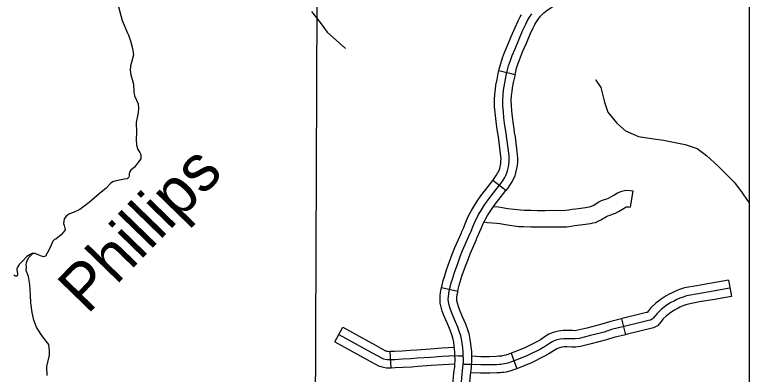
# Model space of a CAD drawing. Extents: x 670147 to 673275, y 705573 to 707613.
# Drawn here: x 672088.3 to 672221.9, y 706242.1 to 706307.4 of the extents above; entities that cross this region are included whole.
import ezdxf

# ---------------------------------------------------------------- set-up
doc = ezdxf.new("R2010")
doc.units = 0
for name, color, linetype in [('31', 7, 'Continuous'), ('32', 7, 'Continuous'), ('35', 7, 'Continuous'), ('45', 7, 'Continuous'), ('46', 7, 'Continuous'), ('5', 7, 'Continuous'), ('R_NoPlot', 7, 'Continuous')]:
    doc.layers.add(name, color=color, linetype=linetype)

msp = doc.modelspace()

# ---------------------------------------------------------------- linework, layer by layer
at = {"layer": '31'}
for p, q in [((672176.39, 706297.26), (672179.32, 706296.57)), ((672177.64, 706275.48), (672175.27, 706277.31)), ((672175.27, 706277.31), (672175.27, 706277.31)), ((672165.96, 706257.83), (672168.89, 706257.16))]:
    msp.add_line(p, q, dxfattribs=at)
for points in [[(672183.1, 706305.95), (672183.21, 706306.16), (672183.61, 706306.7), (672183.96, 706307.18), (672184.57, 706307.76), (672185.16, 706308.23), (672185.81, 706308.68), (672186.41, 706309.04), (672188.06, 706309.98), (672190.48, 706311.09), (672191, 706311.39)], [(672171.76, 706269.14), (672172.18, 706270.11), (672172.42, 706270.58), (672172.7, 706271.12), (672173.05, 706271.68), (672173.39, 706272.25), (672173.78, 706272.84), (672174.32, 706273.61), (672175.19, 706274.75), (672176.73, 706276.75), (672177.14, 706277.33), (672177.45, 706277.82), (672177.66, 706278.21), (672177.85, 706278.66), (672177.98, 706279.07), (672178.14, 706279.76), (672178.22, 706280.19), (672178.27, 706280.74), (672178.28, 706281.28), (672178.23, 706281.82), (672177.85, 706284.93), (672177.71, 706285.81), (672177.42, 706287.68), (672177.3, 706288.69), (672177.2, 706289.8), (672177.1, 706290.85), (672177.08, 706291.86), (672177.15, 706292.9), (672177.24, 706293.68), (672177.34, 706294.38), (672177.52, 706295.37), (672177.73, 706296.4), (672177.92, 706297.19), (672178.16, 706298.15), (672178.49, 706299.09), (672178.83, 706300.04), (672179.32, 706301.24), (672180, 706302.85), (672180.7, 706304.47), (672181.26, 706305.69), (672181.6, 706306.36), (672181.95, 706306.97), (672182.39, 706307.58)], [(672176.39, 706297.26), (672176.46, 706297.55), (672176.73, 706298.58), (672177.07, 706299.58), (672177.42, 706300.57), (672177.93, 706301.82), (672178.63, 706303.44), (672179.33, 706305.08), (672179.91, 706306.34), (672180.28, 706307.07), (672180.48, 706307.43)], [(672179.32, 706296.57), (672179.38, 706296.83), (672179.6, 706297.72), (672179.9, 706298.59), (672180.23, 706299.51), (672180.7, 706300.66), (672181.38, 706302.26), (672182.07, 706303.86), (672182.61, 706305.04), (672182.92, 706305.65), (672183.1, 706305.95)], [(672176.13, 706286.22), (672175.93, 706287.48), (672175.81, 706288.53), (672175.7, 706289.66), (672175.61, 706290.76), (672175.58, 706291.89), (672175.66, 706293.04), (672175.75, 706293.86), (672175.86, 706294.62), (672176.05, 706295.66), (672176.27, 706296.72), (672176.39, 706297.26)], [(672179.32, 706296.57), (672179.2, 706296.08), (672179, 706295.08), (672178.82, 706294.14), (672178.73, 706293.49), (672178.64, 706292.76), (672178.58, 706291.82), (672178.6, 706290.93), (672178.69, 706289.93), (672178.79, 706288.85), (672178.91, 706287.89), (672179.09, 706286.68)], [(672179.09, 706286.68), (672179.19, 706286.04), (672179.34, 706285.14), (672179.73, 706281.98), (672179.78, 706281.32), (672179.77, 706280.66), (672179.71, 706279.99), (672179.61, 706279.44), (672179.43, 706278.67), (672179.26, 706278.15), (672179.02, 706277.56), (672178.74, 706277.06), (672178.38, 706276.5), (672177.94, 706275.86), (672177.64, 706275.48)], [(672175.27, 706277.31), (672175.52, 706277.64), (672175.89, 706278.17), (672176.16, 706278.59), (672176.31, 706278.85), (672176.44, 706279.17), (672176.53, 706279.47), (672176.67, 706280.07), (672176.73, 706280.39), (672176.77, 706280.82), (672176.78, 706281.23), (672176.74, 706281.67), (672176.36, 706284.72), (672176.23, 706285.57), (672176.13, 706286.22)], [(672169.66, 706268.01), (672169.94, 706268.65), (672170.38, 706269.73), (672170.82, 706270.75), (672171.08, 706271.26), (672171.4, 706271.86), (672171.77, 706272.46), (672172.11, 706273.04), (672172.54, 706273.69), (672173.11, 706274.5), (672174, 706275.67), (672175.27, 706277.31)], [(672172.4, 706266.79), (672172.7, 706267.47), (672173.15, 706268.56), (672173.54, 706269.48), (672173.75, 706269.9), (672174, 706270.37), (672174.33, 706270.9), (672174.66, 706271.45), (672175.02, 706272), (672175.53, 706272.73), (672176.38, 706273.84), (672177.64, 706275.48)], [(672165.96, 706257.83), (672166.06, 706258.28), (672166.28, 706259.08), (672166.48, 706259.77), (672166.88, 706261.04), (672167.48, 706262.74), (672167.97, 706264), (672168.39, 706265.11), (672169.56, 706267.8), (672169.66, 706268.01)], [(672169.56, 706240.68), (672169.7, 706242.08), (672169.84, 706243.33), (672169.87, 706243.84), (672169.92, 706244.41), (672169.92, 706244.98), (672169.9, 706245.42), (672169.9, 706246.13), (672169.82, 706246.89), (672169.65, 706248.14), (672169.46, 706249.06), (672169.25, 706249.73), (672168.91, 706250.65), (672168.34, 706251.99), (672167.79, 706253.32), (672167.53, 706254.01), (672167.36, 706254.65), (672167.22, 706255.22), (672167.18, 706255.68), (672167.21, 706256.17), (672167.26, 706256.69), (672167.36, 706257.21), (672167.52, 706257.92), (672167.72, 706258.68), (672167.92, 706259.33), (672168.3, 706260.57), (672168.89, 706262.21), (672169.37, 706263.46), (672169.78, 706264.55), (672170.94, 706267.19), (672171.32, 706268.06), (672171.76, 706269.14)], [(672168.89, 706257.16), (672168.98, 706257.56), (672169.16, 706258.27), (672169.35, 706258.89), (672169.73, 706260.1), (672170.29, 706261.69), (672170.78, 706262.92), (672171.17, 706263.98), (672172.31, 706266.59), (672172.4, 706266.79)], [(672168.27, 706247.19), (672168.18, 706247.88), (672168, 706248.68), (672167.83, 706249.24), (672167.51, 706250.1), (672166.95, 706251.41), (672166.39, 706252.77), (672166.1, 706253.55), (672165.91, 706254.28), (672165.73, 706254.99), (672165.68, 706255.66), (672165.71, 706256.29), (672165.78, 706256.91), (672165.89, 706257.51), (672165.96, 706257.83)], [(672168.89, 706257.16), (672168.83, 706256.91), (672168.75, 706256.48), (672168.7, 706256.05), (672168.69, 706255.7), (672168.7, 706255.46), (672168.81, 706255.03), (672168.96, 706254.47), (672169.19, 706253.87), (672169.72, 706252.57), (672170.3, 706251.2), (672170.67, 706250.21), (672170.91, 706249.45), (672171.13, 706248.39), (672171.24, 706247.58)], [(672167.94, 706236.81), (672167.91, 706237.86), (672167.93, 706238.76), (672167.97, 706239.67), (672168.07, 706240.82), (672168.21, 706242.24), (672168.35, 706243.46), (672168.38, 706243.95), (672168.42, 706244.47), (672168.42, 706244.94), (672168.4, 706245.38), (672168.4, 706246.05), (672168.33, 706246.71), (672168.27, 706247.19)], [(672171.24, 706247.58), (672171.31, 706247.07), (672171.4, 706246.22), (672171.4, 706245.46), (672171.42, 706245.01), (672171.42, 706244.34), (672171.37, 706243.73), (672171.34, 706243.2), (672171.19, 706241.93), (672171.06, 706240.54), (672170.97, 706239.48), (672170.93, 706238.66), (672170.91, 706237.86), (672170.94, 706236.9)]]:
    msp.add_lwpolyline(points, dxfattribs=at)
at = {"layer": '32'}
for p, q in [((672146.56, 706247.98), (672148.01, 706250.61)), ((672156.77, 706243.23), (672156.63, 706246.23))]:
    msp.add_line(p, q, dxfattribs=at)
for points in [[(672148.01, 706250.61), (672153.93, 706247.33), (672155.79, 706246.33), (672155.87, 706246.3), (672156.02, 706246.26), (672156.2, 706246.24), (672156.57, 706246.22), (672156.63, 706246.23)], [(672147.28, 706249.29), (672153.21, 706246.02), (672155.15, 706244.98), (672155.39, 706244.88), (672155.72, 706244.79), (672156.07, 706244.74), (672156.57, 706244.72), (672157.44, 706244.76), (672158.87, 706244.84), (672160.37, 706244.94), (672161.54, 706245.02), (672163.98, 706245.18), (672166.11, 706245.34), (672167.28, 706245.41), (672168.41, 706245.45), (672169.02, 706245.44), (672169.9, 706245.42)], [(672146.56, 706247.98), (672152.49, 706244.7), (672154.51, 706243.62), (672154.9, 706243.45), (672155.42, 706243.32), (672155.94, 706243.25), (672156.57, 706243.22), (672156.77, 706243.23)], [(672156.63, 706246.23), (672157.37, 706246.26), (672158.78, 706246.34), (672160.27, 706246.43), (672161.44, 706246.51), (672163.87, 706246.68), (672166.01, 706246.84), (672168.29, 706246.97)], [(672156.77, 706243.23), (672157.52, 706243.26), (672158.96, 706243.34), (672160.47, 706243.44), (672161.64, 706243.52), (672164.09, 706243.69), (672166.21, 706243.84), (672168.4, 706243.97)]]:
    msp.add_lwpolyline(points, dxfattribs=at)
at = {"layer": '35'}
for points in [[(672108.93, 706303.87), (672107.93, 706306.31), (672107.21, 706309.07)], [(672142.33, 706308.04), (672143.91, 706306.01), (672145.15, 706304.24), (672148.5, 706301.28)], [(672108.93, 706303.87), (672109.4, 706302.7), (672109.77, 706301.29), (672109.94, 706300.15), (672109.6, 706299), (672109.4, 706298.13), (672109.34, 706297.36), (672109.47, 706296.52), (672109.91, 706294.81), (672110.01, 706293.4), (672110.11, 706292.66), (672110.48, 706291.92), (672110.75, 706291.25), (672110.81, 706290.38), (672110.75, 706289.64), (672110.41, 706287.82), (672110.48, 706286.04), (672110.41, 706284.8), (672110.48, 706283.68), (672110.71, 706282.95), (672111.08, 706282.4), (672111.27, 706282.04), (672111.24, 706281.22), (672110.85, 706280.7), (672110.14, 706279.71), (672109.47, 706279.18), (672109.2, 706278.81), (672109.13, 706278.5), (672109.13, 706278.14), (672109.07, 706277.87), (672108.77, 706277.6), (672108.3, 706277.5), (672107.39, 706277.36), (672106.52, 706277.16), (672106.11, 706277.03), (672105.71, 706276.69), (672104.94, 706275.89), (672103.66, 706274.84), (672101.88, 706273.27), (672100.17, 706271.99), (672099.11, 706271.55), (672098.31, 706271.23), (672097.72, 706270.86), (672097.31, 706270.3), (672097.17, 706269.46), (672097.29, 706269.1), (672097.44, 706268.64), (672097.51, 706268.31), (672097.39, 706268.13), (672096.78, 706267.39), (672096.18, 706266.92), (672095.81, 706266.65), (672095.54, 706266.55), (672095.24, 706266.28), (672095.1, 706265.85), (672094.7, 706264.97), (672094.23, 706264.1), (672093.9, 706263.56), (672093.53, 706263.43), (672093.22, 706263.5), (672092.57, 706263.79), (672092.07, 706263.99), (672091.83, 706264.01)], [(672193.97, 706295.62), (672194.03, 706295.55), (672194.9, 706294.18), (672195.62, 706291.5), (672196.2, 706289.7), (672197.86, 706287.68), (672199.44, 706286.31), (672201.75, 706285.29), (672203.7, 706285.01), (672206.3, 706284.64), (672210.27, 706283.85), (672212.44, 706283.13), (672214.17, 706281.83), (672216.26, 706279.88), (672219.22, 706276.92), (672220.64, 706275.07), (672221.54, 706273.73), (672221.93, 706273.25)], [(672091.83, 706264.01), (672091.52, 706263.99), (672091.14, 706263.82), (672090.54, 706263.46), (672089.75, 706262.62), (672089.11, 706262.01), (672088.83, 706261.54), (672088.69, 706261.31), (672088.69, 706260.99), (672088.79, 706260.67), (672088.83, 706260.35), (672088.84, 706260.13), (672088.78, 706259.97), (672088.71, 706259.9), (672088.66, 706259.88), (672088.49, 706259.92), (672088.19, 706260.07)], [(672094.2, 706241.83), (672094.15, 706243.47), (672094.66, 706245.52), (672094.66, 706246.39), (672094.51, 706247.47), (672093.79, 706248.39), (672093.12, 706249.31), (672092.31, 706250.64), (672091.79, 706251.92), (672091.49, 706253.31), (672091.23, 706255.05), (672091.18, 706256.44), (672091.07, 706258.39), (672090.81, 706259.82), (672090.42, 706260.92), (672090.45, 706261.58), (672090.4, 706261.93), (672090.45, 706262.3), (672090.66, 706262.87), (672090.92, 706263.27), (672091.53, 706263.96)]]:
    msp.add_lwpolyline(points, dxfattribs=at)
at = {"layer": '45'}
for p, q in [((672218.17, 706259.17), (672218.68, 706256.22)), ((672198.69, 706252.16), (672199.4, 706249.24)), ((672178.62, 706245.88), (672179.67, 706243.07))]:
    msp.add_line(p, q, dxfattribs=at)
for points in [[(672218.17, 706259.17), (672215.07, 706258.63), (672212.37, 706258.15), (672210.12, 706257.75), (672209.44, 706257.53), (672208.73, 706257.29), (672208, 706256.94), (672207.65, 706256.77), (672207.48, 706256.68)], [(672218.42, 706257.69), (672215.33, 706257.15), (672212.63, 706256.68), (672210.49, 706256.29), (672209.91, 706256.1), (672209.29, 706255.89), (672208.64, 706255.58), (672208.32, 706255.43), (672207.56, 706255.03), (672206.78, 706254.52), (672205.91, 706253.83), (672205.09, 706253.07), (672204.79, 706252.67), (672204.45, 706252.25), (672204.29, 706252.08), (672203.95, 706251.92), (672203.62, 706251.81), (672202.39, 706251.52), (672199.17, 706250.73), (672196.89, 706250.17), (672195.53, 706249.74), (672192.78, 706249.02), (672190.99, 706248.57), (672190.24, 706248.48), (672189.72, 706248.49), (672188.67, 706248.52), (672188.16, 706248.52), (672187.53, 706248.44), (672186.75, 706248.25), (672186.21, 706248), (672185.61, 706247.63), (672184.7, 706247.04), (672183.98, 706246.65), (672181.59, 706245.46), (672179.66, 706244.67), (672178.71, 706244.32), (672178.03, 706244.08), (672177.71, 706244.03), (672177.38, 706243.93), (672177.06, 706243.89), (672176.77, 706243.85), (672176.48, 706243.82), (672175.93, 706243.8), (672174.7, 706243.75), (672173.09, 706243.75), (672171.35, 706243.83), (672169.87, 706243.84)], [(672207.48, 706256.68), (672206.79, 706256.33), (672205.9, 706255.74), (672204.93, 706254.96), (672203.98, 706254.08), (672203.61, 706253.6), (672203.37, 706253.31), (672203.21, 706253.26), (672202.04, 706252.98), (672198.81, 706252.18), (672198.69, 706252.16)], [(672218.68, 706256.22), (672215.59, 706255.67), (672212.89, 706255.2), (672210.86, 706254.83), (672210.39, 706254.68), (672209.86, 706254.5), (672209.29, 706254.23), (672208.98, 706254.09), (672208.87, 706254.03)], [(672208.87, 706254.03), (672208.32, 706253.74), (672207.66, 706253.31), (672206.89, 706252.69), (672206.21, 706252.05), (672205.96, 706251.74), (672205.59, 706251.28), (672205.21, 706250.84), (672204.5, 706250.52), (672204.03, 706250.37), (672202.74, 706250.06), (672199.53, 706249.27), (672199.4, 706249.24)], [(672198.69, 706252.16), (672196.48, 706251.61), (672195.11, 706251.18), (672192.41, 706250.47), (672190.72, 706250.05), (672190.17, 706249.98), (672189.76, 706249.99), (672188.82, 706250.02)], [(672188.82, 706250.02), (672188.69, 706250.02), (672188.06, 706250.02), (672187.25, 706249.91), (672186.26, 706249.67), (672185.5, 706249.33), (672184.81, 706248.9), (672183.93, 706248.33), (672183.28, 706247.98), (672180.97, 706246.83), (672179.11, 706246.07), (672178.62, 706245.88)], [(672199.4, 706249.24), (672197.29, 706248.72), (672195.95, 706248.3), (672193.15, 706247.57), (672191.26, 706247.09), (672190.31, 706246.98), (672189.68, 706246.99), (672188.73, 706247.02)], [(672188.73, 706247.02), (672188.65, 706247.02), (672188.27, 706247.02), (672187.81, 706246.96), (672187.24, 706246.82), (672186.92, 706246.68), (672186.42, 706246.36), (672185.46, 706245.75), (672184.68, 706245.32), (672182.21, 706244.1), (672180.21, 706243.27), (672179.67, 706243.07)], [(672178.62, 706245.88), (672178.21, 706245.73), (672177.66, 706245.54), (672177.36, 706245.49), (672177.06, 706245.4), (672176.87, 706245.37), (672176.6, 706245.34), (672176.36, 706245.32), (672175.87, 706245.3), (672174.68, 706245.25), (672173.12, 706245.25), (672171.4, 706245.33)], [(672179.67, 706243.07), (672179.21, 706242.9), (672178.4, 706242.63), (672178.05, 706242.57), (672177.7, 706242.46), (672177.24, 706242.4), (672176.94, 706242.36), (672176.6, 706242.32), (672175.99, 706242.3), (672174.73, 706242.25), (672173.05, 706242.25), (672171.23, 706242.33)]]:
    msp.add_lwpolyline(points, dxfattribs=at)
at = {"layer": '46'}
for points in [[(672175.4, 706272.56), (672176.33, 706272.5), (672177.01, 706272.4), (672178.02, 706272.22), (672179.14, 706272.09), (672180.31, 706271.94), (672180.96, 706271.9), (672182.22, 706271.89), (672183.42, 706271.86), (672184.82, 706271.85), (672186.97, 706271.88), (672187.99, 706271.86), (672188.51, 706271.88), (672189.08, 706271.95), (672189.74, 706272.07), (672190.32, 706272.14), (672190.87, 706272.19), (672192.13, 706272.35), (672192.42, 706272.41), (672192.83, 706272.51), (672193.02, 706272.55), (672193.51, 706272.77), (672194.55, 706273.4), (672195.03, 706273.63), (672195.62, 706273.84), (672196, 706273.96), (672196.32, 706274.1), (672196.72, 706274.31), (672197.27, 706274.62), (672197.96, 706275.07), (672198.72, 706275.37), (672199.45, 706275.5), (672200.25, 706275.46), (672200.76, 706275.38), (672200.27, 706272.42)], [(672173.68, 706269.79), (672174.25, 706269.67), (672175.24, 706269.56), (672176.01, 706269.52), (672176.53, 706269.44), (672177.58, 706269.26), (672178.77, 706269.11), (672180.03, 706268.95), (672180.86, 706268.9), (672182.18, 706268.89), (672183.38, 706268.86), (672184.82, 706268.85), (672186.97, 706268.88), (672188.03, 706268.86), (672188.75, 706268.89), (672189.53, 706268.99), (672190.18, 706269.1), (672190.64, 706269.15), (672191.21, 706269.21), (672192.59, 706269.39), (672193.05, 706269.47), (672193.5, 706269.58), (672193.97, 706269.68), (672194.91, 706270.12), (672195.98, 706270.76), (672196.18, 706270.85), (672196.6, 706271), (672197.05, 706271.15), (672197.59, 706271.37), (672198.17, 706271.68), (672198.84, 706272.07), (672199.35, 706272.39), (672199.53, 706272.47), (672199.64, 706272.48), (672199.94, 706272.47), (672200.27, 706272.42)]]:
    msp.add_lwpolyline(points, dxfattribs=at)
at = {"layer": '5'}
msp.add_lwpolyline([(672143.33, 706324.68), (672142.94, 706218.97)], dxfattribs=at)
at = {"layer": 'R_NoPlot'}
msp.add_lwpolyline([(671149.93, 706689.36), (672221.93, 706689.36), (672221.93, 705919.71), (671149.93, 705919.71)], close=True, dxfattribs=at)

# ---------------------------------------------------------------- texts
at = {"layer": '35'}
msp.add_text('Phillips', height=8.448, rotation=45.8554, dxfattribs=at).set_placement((672101.55, 706252.79))

doc.saveas('drawing.dxf')
